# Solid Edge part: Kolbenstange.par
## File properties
Username: bmolnar
Dokumentum tartalom típus: 0
Author: bmolnar
Last saved by: bmolnar
Revision: 82
Sűrűség: 0,000 kg/m^3
Pontosság: 0,990
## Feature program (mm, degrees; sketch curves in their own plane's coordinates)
base feature "unnamed BaseFeature 1"
sketch for "unnamed Protrusion 1" plane through (-0.0012, 0, -16.4) normal (0, 0, -1) x-axis (0, -1, 0)
  circle centre (0, -0.0012) radius 16
extrude "unnamed Protrusion 1" add finite 8.35 along +normal
sketch for "Furat_1" plane through (0, 0, 28.9) normal (0, 0, 1) x-axis (0, 1, 0)
  hole centre (0, 0) bore radius 2.4585
hole "Furat_1" nominal diameter 6 finite  VBottomAngle = 118 deg; ThreadDepth = 12.5 mm
chamfer "Letörés_1" setback 0.5  SetBackValue2 = 45 deg
sketch for "Kihúzás_3" #1 plane through (0, 0, -16.4) normal (0, 0, 1) x-axis (0, 1, 0)
  circle centre (0, 0) radius 6
sketch for "Kihúzás_3" #2 plane through (0, 0, -16.4) normal (0, 0, 1) x-axis (0, 1, 0)
  circle centre (0, 0) radius 16
extrude "Kihúzás_3" add finite 22.65 along +normal
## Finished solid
Body 1: solid body, 17 faces, 23 edges, 8 vertices.
  Faces by surface: plane 7, cylinder 5, cone 3, torus 2
  Edges by curve: circle 13, line 6, curve on surface 2, ellipse 2
Bounding box of the edges (mm; curved faces can reach further): 32.000 x 32.000 x 56.150, from (-16, -16, -24.75) to (16, 16, 31.4).
Cylindrical faces by radius (mm): R2.4585 x2, R3.125 x1, R6 x1, R16 x1
Conical faces (half-angle, radius in mm at the cone's reference point): 45 deg R2.9585 x1, 45 deg R3.225 x1, 59 deg R2.4585 x1
Toroidal faces (ring radius, tube radius in mm): R2.925 r0.2 x1, R4.7 r1.3 x1
Planar faces by outward normal: +x 1, +z 2, -x 1, -z 1, oblique 2
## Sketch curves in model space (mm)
circle centre (0, 0, -16.4) radius 16
circle centre (0, 0, -16.4) radius 6
circle centre (0, 0, -16.4) radius 16
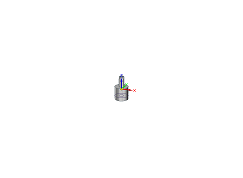
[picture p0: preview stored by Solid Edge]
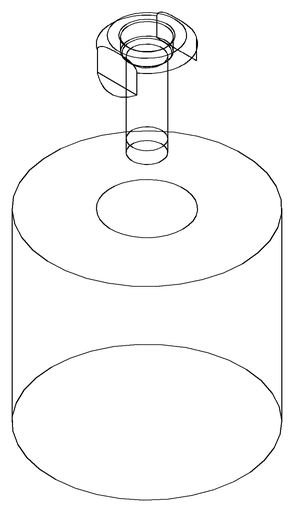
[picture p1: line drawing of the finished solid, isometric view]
